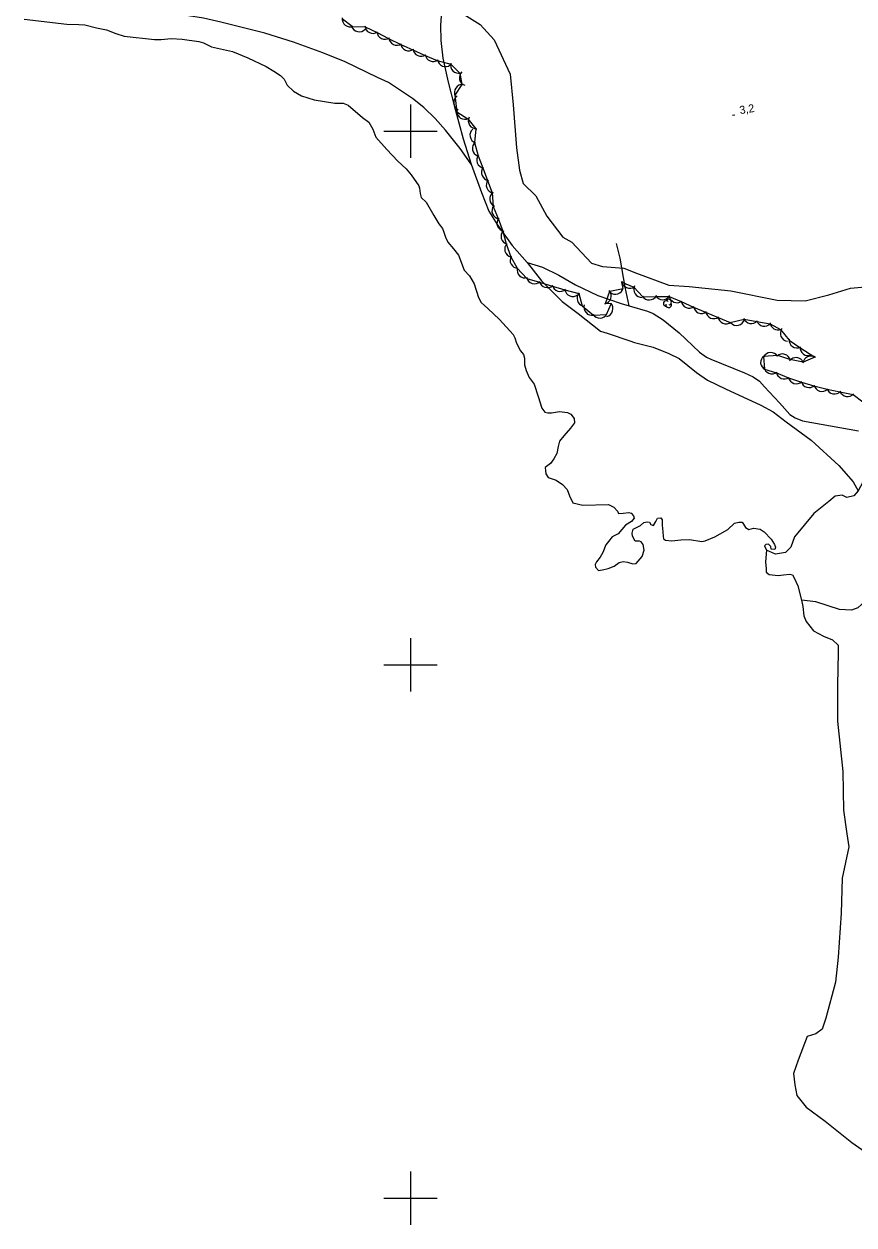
# Model space of a CAD drawing. Extents: x 643342 to 646936, y 5873857 to 5876103.
# Drawn here: x 644255.1 to 644566.3, y 5874790 to 5875240.2 of the extents above; entities that cross this region are included whole.
import ezdxf

# ---------------------------------------------------------------- set-up
doc = ezdxf.new("R2010")
doc.units = 0
for name, color, linetype in [('Niveau 2', 7, 'Continuous'), ('Niveau 22', 7, 'Continuous'), ('Niveau 3', 7, 'Continuous'), ('Niveau 4', 7, 'Continuous'), ('Niveau 44', 7, 'Continuous'), ('Niveau 61', 7, 'Continuous')]:
    doc.layers.add(name, color=color, linetype=linetype)

msp = doc.modelspace()

# ---------------------------------------------------------------- linework, layer by layer
at = {"layer": 'Niveau 2'}
msp.add_lwpolyline([(644420.07, 5875243.79), (644426.09, 5875239.97), (644431.35, 5875234.18), (644437.38, 5875221.36), (644438.46, 5875209.84), (644439.72, 5875193.71), (644440.85, 5875185.4), (644442.25, 5875180.43), (644446.93, 5875175.78), (644451.07, 5875168.11), (644457.11, 5875160.26), (644460.48, 5875158.33), (644467.82, 5875150.49), (644471.94, 5875149.29), (644479.96, 5875148.69), (644484.69, 5875146.71), (644496.89, 5875142.31), (644504.43, 5875141.79), (644520.02, 5875140.2), (644537.43, 5875136.66), (644547.94, 5875136.43), (644556.8, 5875138.7), (644564.93, 5875141.14), (644575.89, 5875142.19)], dxfattribs=at)
at = {"layer": 'Niveau 22'}
for points in [[(644422.75, 5875187.65), (644418.65, 5875193.55), (644413.15, 5875200.38), (644409.2, 5875204.69), (644404.96, 5875208.88), (644400.68, 5875212.28), (644391.7, 5875218.28), (644387.54, 5875220.12), (644375.43, 5875225.97), (644367.04, 5875229.36), (644356.14, 5875233.35), (644345.4, 5875236.76), (644328.9, 5875240.91), (644322.32, 5875242.38), (644316.67, 5875243.23), (644307.18, 5875244.18), (644296.26, 5875244.64), (644289.03, 5875244.2), (644277.49, 5875243.82)], [(644411.64, 5875244.86), (644411.17, 5875239.72), (644411.35, 5875234.04), (644412.09, 5875227.35), (644414.1, 5875218.4), (644416.5, 5875209.13), (644419.74, 5875197.09), (644422.75, 5875187.65), (644426.58, 5875176.97), (644429.35, 5875169.99), (644432.41, 5875165.06), (644438.11, 5875157.17), (644443.66, 5875150.81), (644449.15, 5875143.86), (644456.84, 5875136.16), (644462.81, 5875131.63), (644471.22, 5875125.08), (644473.66, 5875124.24), (644482.25, 5875121.42), (644484.02, 5875120.84), (644490.92, 5875119.01), (644496.81, 5875116.61), (644500.76, 5875114.74), (644507.26, 5875109.55), (644511.31, 5875106.61), (644518.1, 5875103.47), (644531.3, 5875097.26), (644535.9, 5875094.74), (644540.85, 5875091.06), (644550.22, 5875084.13), (644560.54, 5875074.69), (644565.94, 5875068.56), (644567.86, 5875065.24)], [(644481.91, 5875134.54), (644480.43, 5875141.52), (644478.59, 5875152.37), (644477.25, 5875157.94)], [(644443.66, 5875150.81), (644449.5, 5875149), (644455.57, 5875146.02), (644461.81, 5875142.34), (644470.21, 5875138.4), (644478.99, 5875135.44), (644481.91, 5875134.54), (644488.78, 5875132.5), (644491, 5875131.68), (644494.71, 5875129.31), (644500.67, 5875124.37), (644508.37, 5875117.2), (644510.97, 5875115.34), (644512.6, 5875114.48), (644525.24, 5875109.44), (644528.5, 5875107.92), (644530.77, 5875106.33), (644532.7, 5875104.22), (644538.36, 5875098.17), (644542.22, 5875093.75), (644544.18, 5875092.52), (644547.01, 5875091.36), (644553.98, 5875090.12), (644567.9, 5875087.72)]]:
    msp.add_lwpolyline(points, dxfattribs=at)
at = {"layer": 'Niveau 3'}
msp.add_line((644520.73, 5875205.96), (644521.52, 5875206.09), dxfattribs=at)
at = {"layer": 'Niveau 4'}
for points in [[(644255.05, 5875242.02), (644271.13, 5875240.09), (644275.65, 5875240.04), (644277.91, 5875239.9), (644282.29, 5875238.77), (644286.04, 5875237.94), (644289.49, 5875236.6), (644292.55, 5875235.58), (644304.04, 5875234.41), (644306.53, 5875234.4), (644310.29, 5875234.76)], [(644310.29, 5875234.76), (644314.35, 5875234.43), (644320.59, 5875233.59), (644322.29, 5875233.16), (644325.39, 5875231.67), (644333.26, 5875229.8), (644338.93, 5875227.48), (644345.86, 5875224.22), (644348.75, 5875222.47), (644351.27, 5875220.81), (644352.58, 5875219.51), (644353.73, 5875217.24), (644356.08, 5875214.97), (644359.08, 5875213.23), (644363.83, 5875211.78), (644371.65, 5875210.5), (644374.73, 5875210.44), (644376.57, 5875209.78), (644381.97, 5875205.07), (644384.38, 5875203.4), (644385.8, 5875200.8), (644386.91, 5875197.81), (644391.13, 5875193.11), (644395.21, 5875188.74), (644398.32, 5875185.83), (644400.18, 5875183.63), (644403.04, 5875179.51), (644403.37, 5875178.59), (644403.55, 5875176.58), (644403.92, 5875175.19), (644405.86, 5875173.36), (644408.69, 5875168.4), (644410.64, 5875165.26), (644411.98, 5875163.48), (644412.47, 5875162.1), (644413.11, 5875160.26), (644414, 5875158.33), (644416.12, 5875155.92), (644418, 5875153.48), (644420.06, 5875147.86), (644422.15, 5875145.8), (644423.85, 5875142.75), (644425.5, 5875137.68), (644426.51, 5875135.76), (644428.97, 5875133.5), (644433.37, 5875129.4), (644438.51, 5875123.72), (644439.09, 5875122.58), (644439.75, 5875120.51), (644441.2, 5875117.67), (644442.4, 5875116.24), (644442.76, 5875114.85), (644442.76, 5875112.36), (644443.31, 5875110.27), (644444.5, 5875107.65), (644446.38, 5875105.22), (644447.88, 5875100.49), (644449.22, 5875096.22), (644450.32, 5875094.66), (644451.4, 5875094.41), (644452.82, 5875094.43), (644455.85, 5875094.96), (644458.84, 5875094.53), (644460.08, 5875093.94), (644461.3, 5875092.27)], [(644461.3, 5875092.27), (644461.45, 5875090.62), (644459.98, 5875088.7), (644457.52, 5875085.84), (644455.82, 5875083.78), (644455.29, 5875081.82), (644454.83, 5875079.16), (644453.72, 5875077.15), (644452.45, 5875075.49), (644450.46, 5875073.98), (644450.58, 5875072.69), (644450.69, 5875071.51), (644451.53, 5875070.16), (644454.58, 5875069.15), (644456.97, 5875067.6), (644458.68, 5875065.74), (644459.61, 5875063.34), (644460.8, 5875060.72), (644464.56, 5875059.77), (644474.22, 5875060.12), (644476.2, 5875059.12), (644477.53, 5875057.58), (644477.97, 5875056.67), (644479.73, 5875056.84), (644481.83, 5875057.05), (644482.69, 5875056.78), (644483.61, 5875055.79), (644483.8, 5875054.98), (644482.86, 5875053.7), (644480.62, 5875052.29), (644477.85, 5875049.05), (644475.6, 5875047.88), (644474.22, 5875046.2), (644473.15, 5875044.91), (644472.12, 5875042.07), (644471.1, 5875040.31), (644469.72, 5875038.63), (644469.23, 5875037.51), (644469.32, 5875036.57), (644470.49, 5875035.37), (644471.9, 5875035.51), (644474.09, 5875036.08), (644476.38, 5875036.9), (644478.15, 5875038.26), (644479.76, 5875038.66), (644481.32, 5875038.45), (644483.39, 5875037.82), (644484.56, 5875037.93), (644486.8, 5875040.53), (644487.64, 5875042.99), (644487.2, 5875045.09), (644486.52, 5875046.09), (644485.79, 5875046.26), (644484.25, 5875046.35), (644483.25, 5875048.15), (644483.14, 5875049.33), (644483.48, 5875050.79), (644486.18, 5875052.24), (644487.5, 5875053.32), (644488.66, 5875053.55), (644489.62, 5875053.41), (644490.05, 5875052.62), (644491.03, 5875052.24), (644491.96, 5875053.63), (644492.54, 5875055)], [(644590.18, 5875081.17), (644582.86, 5875077.62), (644576.32, 5875074.37), (644572.26, 5875072.43), (644570.58, 5875070.25), (644567.86, 5875065.24), (644566.16, 5875063.29), (644563.62, 5875062.69), (644561.77, 5875063.58), (644559.21, 5875063.21), (644556.8, 5875061.2), (644551.2, 5875056.73), (644544, 5875047.95), (644542.58, 5875044.13), (644540.54, 5875042.03), (644536.81, 5875041.43), (644533.47, 5875042.93)], [(644492.54, 5875055), (644493.83, 5875055.12), (644494.38, 5875054.34), (644494.34, 5875052.2), (644494.44, 5875051.14), (644494.71, 5875048.19), (644494.8, 5875047.25), (644495.56, 5875046.73), (644497.95, 5875046.49), (644501.34, 5875046.82), (644504.64, 5875046.9), (644509.2, 5875046.16), (644510.48, 5875046.4), (644514.11, 5875047.94), (644518.94, 5875050.67), (644521.43, 5875053.05), (644523.05, 5875053.44), (644524.35, 5875053.45), (644524.89, 5875052.67), (644525.6, 5875051.43), (644526.84, 5875050.72), (644528.58, 5875051.13), (644531.09, 5875050.78), (644532.59, 5875049.86), (644535.22, 5875047.02), (644536.46, 5875045.12), (644536.79, 5875044.08), (644536.52, 5875043.23), (644535.21, 5875043.34), (644535.12, 5875044.28), (644534.21, 5875045.14), (644533.16, 5875045.04), (644532.73, 5875044.52), (644533.47, 5875042.93), (644533.05, 5875038.61), (644533.3, 5875035.9), (644533.3, 5875034.71), (644534.44, 5875033.87), (644537.78, 5875033.49), (644539.77, 5875033.68), (644542.22, 5875033.92), (644543.19, 5875033.66), (644543.77, 5875032.52), (644545.23, 5875029.58), (644546.54, 5875024.22), (644547.13, 5875021.8), (644547.46, 5875018.27), (644548.36, 5875016.21), (644551.06, 5875012.67), (644554.78, 5875010.66), (644558.21, 5875009.33), (644560.28, 5875007.39), (644560.31, 5875004.55), (644560.03, 5874992.39), (644560.12, 5874978.85), (644562.11, 5874960.02), (644562.29, 5874945.53), (644563.59, 5874936.62), (644564.29, 5874931.69), (644561.83, 5874920.03), (644561.41, 5874906.9), (644560.35, 5874890.37), (644559.34, 5874880.98), (644555.64, 5874867.52), (644554.37, 5874863.35)], [(644607.01, 5875046.17), (644599.62, 5875039.51), (644592.72, 5875033.97), (644590.47, 5875032.81), (644587.92, 5875032.32), (644585.4, 5875032.79), (644583.82, 5875034.65), (644582.53, 5875034.52), (644581.6, 5875033.13), (644579.31, 5875031.12), (644576.45, 5875030.25), (644573.89, 5875028.58), (644572.41, 5875025.46), (644570.44, 5875023.84), (644567.73, 5875021.32), (644565.33, 5875020.49), (644560.83, 5875020.65), (644551.94, 5875023.58), (644546.54, 5875024.22)], [(644554.37, 5874863.35), (644551.93, 5874861.68), (644548.72, 5874860.64), (644545.29, 5874851.73), (644543.63, 5874846.8), (644544.02, 5874842.55), (644544.87, 5874838.58), (644548.35, 5874834.17), (644555.46, 5874828.92), (644565.43, 5874820.87), (644574.26, 5874814.85)]]:
    msp.add_lwpolyline(points, dxfattribs=at)
at = {"layer": 'Niveau 44'}
for points in [[(644374.3, 5875242.17), (644378.18, 5875239.27), (644382.94, 5875239.14), (644387.42, 5875236.93), (644391.77, 5875234.79), (644396.38, 5875232.46), (644400.83, 5875230.51), (644405.53, 5875228.4), (644410.01, 5875226.54), (644415.04, 5875225.17), (644418.46, 5875221.73), (644419.27, 5875217.53), (644416.63, 5875213.46), (644417.38, 5875207.26), (644421.48, 5875204.67), (644424.5, 5875200.92), (644423.95, 5875195.79), (644425.31, 5875190.79), (644427.04, 5875186.26), (644428.87, 5875181.45), (644430.6, 5875176.92), (644430.96, 5875171.76)], [(644430.96, 5875171.76), (644432.78, 5875167.26), (644434.55, 5875162.46), (644435.88, 5875157.79), (644437.59, 5875152.9), (644439.95, 5875148.66), (644443.63, 5875144.77), (644448.28, 5875143.39), (644453.22, 5875141.92), (644457.87, 5875140.54), (644463.05, 5875139.19), (644464.39, 5875134.53), (644468.59, 5875131.01), (644473.43, 5875131.29), (644475.26, 5875135.28), (644473.1, 5875135.38), (644474.68, 5875139.97), (644479.67, 5875141.01), (644479.25, 5875143.43), (644483.71, 5875141.53), (644487.1, 5875137.88), (644491.95, 5875138.06), (644496.99, 5875138.06), (644501.43, 5875136.09), (644506.13, 5875133.99), (644510.61, 5875132.1), (644515.35, 5875130.1), (644519.82, 5875128.22), (644525.03, 5875129.59), (644529.79, 5875128.66), (644534.84, 5875127.84), (644538.74, 5875125.69), (644541.89, 5875121.69), (644545.89, 5875118.93), (644551.6, 5875115.33), (644547.17, 5875113.35), (644542.26, 5875114.42), (644537.64, 5875115.91), (644532.27, 5875115.59), (644532.72, 5875110.76), (644537.2, 5875109.4), (644541.68, 5875107.54), (644546.58, 5875105.88), (644551.23, 5875104.5), (644556.24, 5875103.23), (644561, 5875102.28), (644565.9, 5875101.29), (644569.6, 5875098.54)]]:
    msp.add_lwpolyline(points, dxfattribs=at)
for centre, radius, start, end in [((644377.3, 5875242.13), 3, 173.2122, 293.1901), ((644377.3, 5875242.13), 3, 173.2122, 293.1901), ((644377.3, 5875242.13), 3, 173.2122, 293.1901), ((644380.69, 5875240.25), 3, 199.2474, 319.2253), ((644380.69, 5875240.25), 3, 199.2474, 319.2253), ((644380.69, 5875240.25), 3, 199.2474, 319.2253), ((644385.89, 5875239.65), 3, 183.7612, 303.7391), ((644385.89, 5875239.65), 3, 183.7612, 303.7391), ((644385.89, 5875239.65), 3, 183.7612, 303.7391), ((644390.38, 5875237.44), 3, 183.7612, 303.7391), ((644390.38, 5875237.44), 3, 183.7612, 303.7391), ((644390.38, 5875237.44), 3, 183.7612, 303.7391), ((644394.86, 5875235.23), 3, 183.7612, 303.7391), ((644394.86, 5875235.23), 3, 183.7612, 303.7391), ((644394.86, 5875235.23), 3, 183.7612, 303.7391), ((644399.31, 5875233.1), 3, 186.3191, 306.2971), ((644399.31, 5875233.1), 3, 186.3191, 306.2971), ((644399.31, 5875233.1), 3, 186.3191, 306.2971), ((644403.89, 5875231.09), 3, 186.3191, 306.2971), ((644403.89, 5875231.09), 3, 186.3191, 306.2971), ((644403.89, 5875231.09), 3, 186.3191, 306.2971), ((644408.44, 5875229.1), 3, 187.4942, 307.4721), ((644408.44, 5875229.1), 3, 187.4942, 307.4721), ((644408.44, 5875229.1), 3, 187.4942, 307.4721), ((644413.06, 5875227.19), 3, 187.4942, 307.4721), ((644413.06, 5875227.19), 3, 187.4942, 307.4721), ((644413.06, 5875227.19), 3, 187.4942, 307.4721), ((644418, 5875224.7), 3, 164.8649, 284.8429), ((644418, 5875224.7), 3, 164.8649, 284.8429), ((644418, 5875224.7), 3, 164.8649, 284.8429), ((644421.28, 5875220.07), 3, 132.7314, 252.7093), ((644421.28, 5875220.07), 3, 132.7314, 252.7093), ((644421.28, 5875220.07), 3, 132.7314, 252.7093), ((644419.43, 5875214.54), 3, 87.0367, 207.0147), ((644419.43, 5875214.54), 3, 87.0367, 207.0147), ((644419.43, 5875214.54), 3, 87.0367, 207.0147), ((644419.15, 5875210.75), 3, 125.3279, 245.3058), ((644419.15, 5875210.75), 3, 125.3279, 245.3058), ((644419.15, 5875210.75), 3, 125.3279, 245.3058), ((644420.37, 5875207.45), 3, 177.7218, 297.6997), ((644420.37, 5875207.45), 3, 177.7218, 297.6997), ((644420.37, 5875207.45), 3, 177.7218, 297.6997), ((644424.64, 5875203.92), 3, 153.3281, 273.306), ((644424.64, 5875203.92), 3, 153.3281, 273.306), ((644424.64, 5875203.92), 3, 153.3281, 273.306), ((644425.24, 5875198.49), 3, 130.5025, 250.4805), ((644425.24, 5875198.49), 3, 130.5025, 250.4805), ((644425.24, 5875198.49), 3, 130.5025, 250.4805), ((644426.15, 5875193.58), 3, 130.5025, 250.4805), ((644426.15, 5875193.58), 3, 130.5025, 250.4805), ((644426.15, 5875193.58), 3, 130.5025, 250.4805), ((644427.82, 5875189.16), 3, 140.9014, 260.8793), ((644427.82, 5875189.16), 3, 140.9014, 260.8793), ((644427.82, 5875189.16), 3, 140.9014, 260.8793), ((644429.6, 5875184.48), 3, 140.9014, 260.8793), ((644429.6, 5875184.48), 3, 140.9014, 260.8793), ((644429.6, 5875184.48), 3, 140.9014, 260.8793), ((644431.38, 5875179.81), 3, 140.9014, 260.8793), ((644431.38, 5875179.81), 3, 140.9014, 260.8793), ((644431.38, 5875179.81), 3, 140.9014, 260.8793), ((644432.67, 5875174.61), 3, 125.3339, 245.3118), ((644432.67, 5875174.61), 3, 125.3339, 245.3118), ((644432.67, 5875174.61), 3, 125.3339, 245.3118), ((644433.5, 5875170.17), 3, 142.0548, 262.0328), ((644433.5, 5875170.17), 3, 142.0548, 262.0328), ((644433.5, 5875170.17), 3, 142.0548, 262.0328), ((644435.38, 5875165.53), 3, 142.0548, 262.0328), ((644435.38, 5875165.53), 3, 142.0548, 262.0328), ((644435.38, 5875165.53), 3, 142.0548, 262.0328), ((644436.91, 5875160.61), 3, 135.9495, 255.9274), ((644436.91, 5875160.61), 3, 135.9495, 255.9274), ((644436.91, 5875160.61), 3, 135.9495, 255.9274), ((644438.28, 5875155.8), 3, 135.9495, 255.9274), ((644438.28, 5875155.8), 3, 135.9495, 255.9274), ((644438.28, 5875155.8), 3, 135.9495, 255.9274), ((644440.31, 5875151.64), 3, 149.1201, 269.0981), ((644440.31, 5875151.64), 3, 149.1201, 269.0981), ((644440.31, 5875151.64), 3, 149.1201, 269.0981), ((644442.94, 5875147.99), 3, 166.3251, 286.303), ((644442.94, 5875147.99), 3, 166.3251, 286.303), ((644442.94, 5875147.99), 3, 166.3251, 286.303), ((644446.46, 5875145.77), 3, 193.4864, 313.4644), ((644446.46, 5875145.77), 3, 193.4864, 313.4644), ((644446.46, 5875145.77), 3, 193.4864, 313.4644), ((644451.25, 5875144.35), 3, 193.4864, 313.4644), ((644451.25, 5875144.35), 3, 193.4864, 313.4644), ((644451.25, 5875144.35), 3, 193.4864, 313.4644), ((644456.04, 5875142.92), 3, 193.4864, 313.4644), ((644456.04, 5875142.92), 3, 193.4864, 313.4644), ((644456.04, 5875142.92), 3, 193.4864, 313.4644), ((644482.17, 5875144.1), 3, 186.8987, 306.8766), ((644482.17, 5875144.1), 3, 186.8987, 306.8766), ((644482.17, 5875144.1), 3, 186.8987, 306.8766), ((644486.68, 5875140.69), 3, 153.9932, 273.9712), ((644486.68, 5875140.69), 3, 153.9932, 273.9712), ((644486.68, 5875140.69), 3, 153.9932, 273.9712), ((644460.84, 5875141.04), 3, 187.6344, 307.6124), ((644460.84, 5875141.04), 3, 187.6344, 307.6124), ((644460.84, 5875141.04), 3, 187.6344, 307.6124), ((644465.42, 5875137.35), 3, 136.053, 256.031), ((644465.42, 5875137.35), 3, 136.053, 256.031), ((644465.42, 5875137.35), 3, 136.053, 256.031), ((644472.23, 5875138.25), 3, 281.0363, 41.0143), ((644472.23, 5875138.25), 3, 281.0363, 41.0143), ((644472.23, 5875138.25), 3, 281.0363, 41.0143), ((644476.8, 5875141.89), 3, 228.8883, 348.8662), ((644476.8, 5875141.89), 3, 228.8883, 348.8662), ((644476.8, 5875141.89), 3, 228.8883, 348.8662), ((644489.45, 5875139.73), 3, 212.1878, 332.1658), ((644489.45, 5875139.73), 3, 212.1878, 332.1658), ((644489.45, 5875139.73), 3, 212.1878, 332.1658), ((644494.56, 5875139.8), 3, 208.1608, 328.1388), ((644494.56, 5875139.8), 3, 208.1608, 328.1388), ((644494.56, 5875139.8), 3, 208.1608, 328.1388), ((644499.93, 5875138.69), 3, 186.0157, 305.9937), ((644499.93, 5875138.69), 3, 186.0157, 305.9937), ((644499.93, 5875138.69), 3, 186.0157, 305.9937), ((644468, 5875133.98), 3, 162.1305, 282.1084), ((644468, 5875133.98), 3, 162.1305, 282.1084), ((644468, 5875133.98), 3, 162.1305, 282.1084), ((644472.88, 5875133.46), 3, 283.2178, 43.1957), ((644472.88, 5875133.46), 3, 283.2178, 43.1957), ((644472.88, 5875133.46), 3, 283.2178, 43.1957), ((644495.84, 5875135.42), 1.05, 44.1154, 269.804), ((644496.74, 5875134.9), 1.05, 166.9369, 29.6212), ((644496.74, 5875135.95), 1.05, 282.2692, 149.7263), ((644504.5, 5875136.65), 3, 186.0157, 305.9937), ((644504.5, 5875136.65), 3, 186.0157, 305.9937), ((644504.5, 5875136.65), 3, 186.0157, 305.9937), ((644509.05, 5875134.67), 3, 187.1483, 307.1262), ((644509.05, 5875134.67), 3, 187.1483, 307.1262), ((644509.05, 5875134.67), 3, 187.1483, 307.1262), ((644470.91, 5875132.91), 3, 213.3782, 333.3561), ((644470.91, 5875132.91), 3, 213.3782, 333.3561), ((644470.91, 5875132.91), 3, 213.3782, 333.3561), ((644513.66, 5875132.73), 3, 187.1483, 307.1262), ((644513.66, 5875132.73), 3, 187.1483, 307.1262), ((644513.66, 5875132.73), 3, 187.1483, 307.1262), ((644518.27, 5875130.79), 3, 187.1483, 307.1262), ((644518.27, 5875130.79), 3, 187.1483, 307.1262), ((644518.27, 5875130.79), 3, 187.1483, 307.1262), ((644522.24, 5875130.19), 3, 223.4669, 343.4448), ((644522.24, 5875130.19), 3, 223.4669, 343.4448), ((644522.24, 5875130.19), 3, 223.4669, 343.4448), ((644527.75, 5875130.86), 3, 198.9831, 318.9611), ((644527.75, 5875130.86), 3, 198.9831, 318.9611), ((644527.75, 5875130.86), 3, 198.9831, 318.9611), ((644532.66, 5875129.9), 3, 198.9831, 318.9611), ((644532.66, 5875129.9), 3, 198.9831, 318.9611), ((644532.66, 5875129.9), 3, 198.9831, 318.9611), ((644537.76, 5875128.52), 3, 187.1607, 290.2944), ((644537.76, 5875128.52), 3, 187.1607, 290.2944), ((644537.76, 5875128.52), 3, 187.1607, 290.2944), ((644541.63, 5875124.24), 3, 143.7067, 263.6847), ((644541.63, 5875124.24), 3, 143.7067, 263.6847), ((644541.63, 5875124.24), 3, 143.7067, 263.6847), ((644544.89, 5875121.76), 3, 175.3936, 295.3715), ((644544.89, 5875121.76), 3, 175.3936, 295.3715), ((644544.89, 5875121.76), 3, 175.3936, 295.3715), ((644534.25, 5875113.34), 3, 125.3554, 245.3334), ((644534.25, 5875113.34), 3, 125.3554, 245.3334), ((644534.25, 5875113.34), 3, 125.3554, 245.3334), ((644535.06, 5875114.02), 3, 32.7844, 152.7624), ((644535.06, 5875114.02), 3, 32.7844, 152.7624), ((644535.06, 5875114.02), 3, 32.7844, 152.7624), ((644539.41, 5875113.49), 3, 12.1762, 132.1542), ((644539.41, 5875113.49), 3, 12.1762, 132.1542), ((644539.41, 5875113.49), 3, 12.1762, 132.1542), ((644544.52, 5875112.12), 3, 24.1442, 144.1222), ((644544.52, 5875112.12), 3, 24.1442, 144.1222), ((644544.52, 5875112.12), 3, 24.1442, 144.1222), ((644549.01, 5875118.92), 3, 175.3936, 295.3715), ((644549.01, 5875118.92), 3, 175.3936, 295.3715), ((644549.01, 5875118.92), 3, 175.3936, 295.3715), ((644550.1, 5875112.73), 3, 54.0545, 174.0325), ((644550.1, 5875112.73), 3, 54.0545, 174.0325), ((644550.1, 5875112.73), 3, 54.0545, 174.0325), ((644535.51, 5875112.02), 3, 187.3979, 307.3758), ((644535.51, 5875112.02), 3, 187.3979, 307.3758), ((644535.51, 5875112.02), 3, 187.3979, 307.3758), ((644540.12, 5875110.1), 3, 187.3979, 307.3758), ((644540.12, 5875110.1), 3, 187.3979, 307.3758), ((644540.12, 5875110.1), 3, 187.3979, 307.3758), ((644544.61, 5875108.3), 3, 193.4724, 313.4503), ((644544.61, 5875108.3), 3, 193.4724, 313.4503), ((644544.61, 5875108.3), 3, 193.4724, 313.4503), ((644549.41, 5875106.88), 3, 193.4724, 313.4503), ((644549.41, 5875106.88), 3, 193.4724, 313.4503), ((644549.41, 5875106.88), 3, 193.4724, 313.4503), ((644554.2, 5875105.46), 3, 193.4724, 313.4503), ((644554.2, 5875105.46), 3, 193.4724, 313.4503), ((644554.2, 5875105.46), 3, 193.4724, 313.4503), ((644558.96, 5875104.48), 3, 198.6661, 318.6441), ((644558.96, 5875104.48), 3, 198.6661, 318.6441), ((644558.96, 5875104.48), 3, 198.6661, 318.6441), ((644563.87, 5875103.5), 3, 198.6661, 318.6441), ((644563.87, 5875103.5), 3, 198.6661, 318.6441), ((644563.87, 5875103.5), 3, 198.6661, 318.6441)]:
    msp.add_arc(centre, radius, start, end, dxfattribs=at)
at = {"layer": 'Niveau 61'}
for points in [[(644400, 5875210), (644400, 5875200), (644400, 5875190)], [(644390, 5875200), (644400, 5875200), (644410, 5875200)], [(644400, 5875010), (644400, 5875000), (644400, 5874990)], [(644390, 5875000), (644400, 5875000), (644410, 5875000)], [(644400, 5874810), (644400, 5874800), (644400, 5874790)], [(644390, 5874800), (644400, 5874800), (644410, 5874800)]]:
    msp.add_lwpolyline(points, dxfattribs=at)

# ---------------------------------------------------------------- texts
at = {"layer": 'Niveau 3'}
msp.add_text('3,2  ', height=3, rotation=8.941, dxfattribs=at).set_placement((644523.58, 5875206.37))

doc.saveas('drawing.dxf')
